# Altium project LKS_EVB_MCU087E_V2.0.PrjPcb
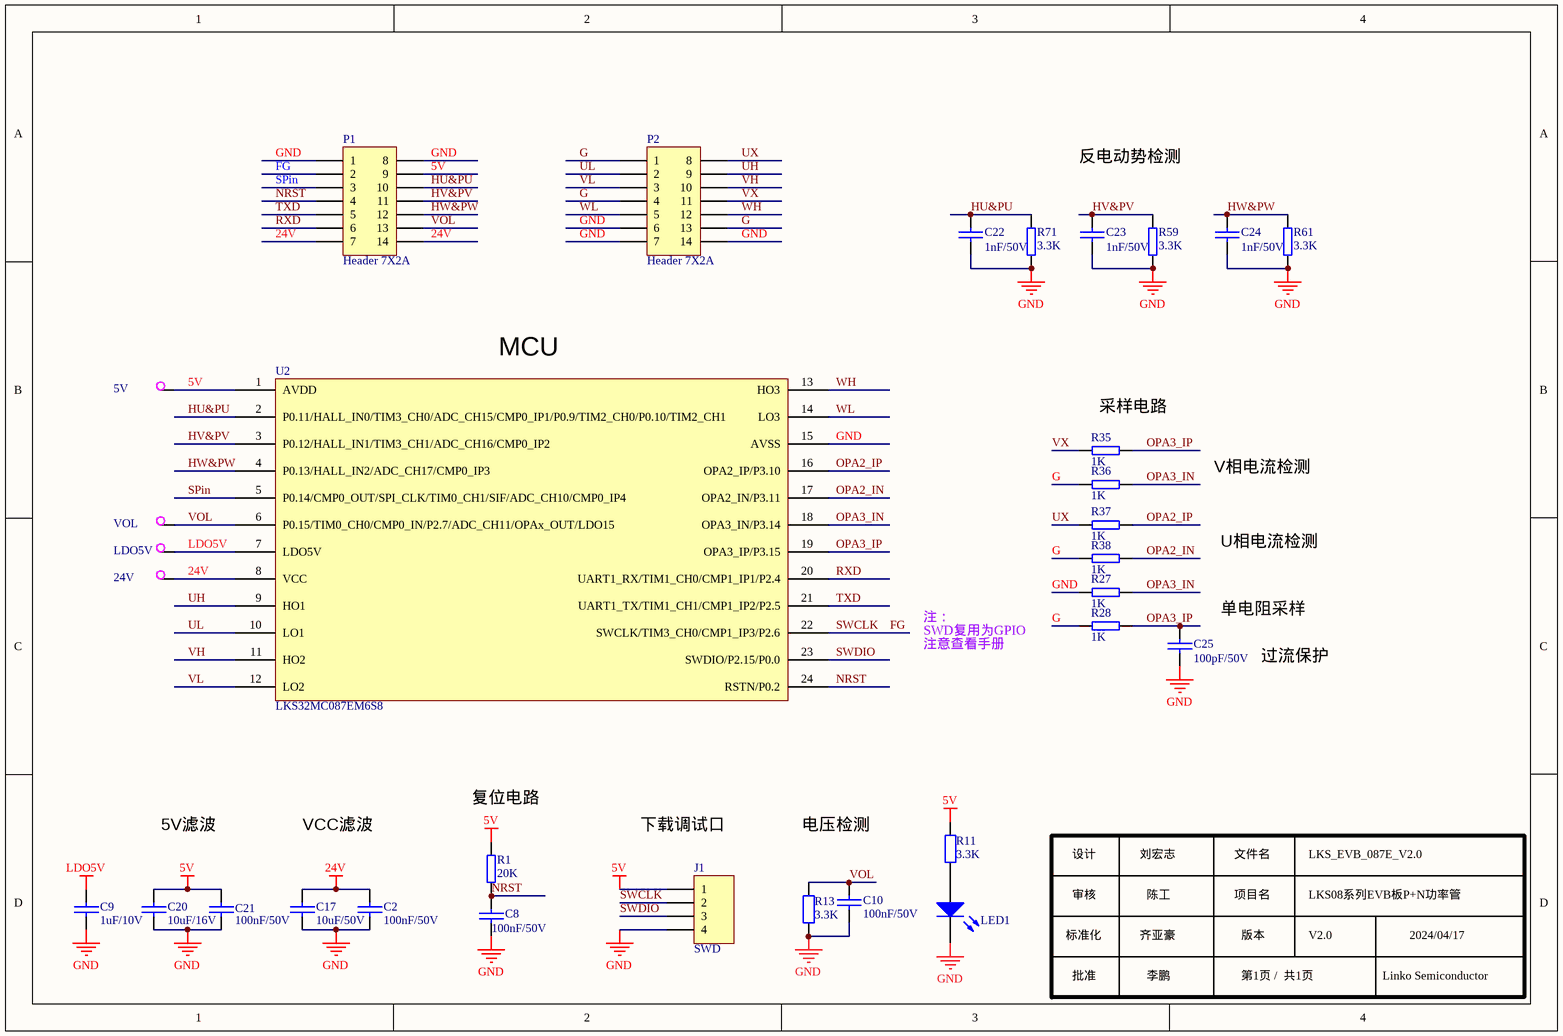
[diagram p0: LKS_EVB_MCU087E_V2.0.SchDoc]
1 sheet, 32 parts. Net scope: global (net labels, ports and power ports of the same name join across sheets).
Board file: LKS_EVB_MCU087E_V2.0.PcbDoc

## Sheet LKS_EVB_MCU087E_V2.0.SchDoc: LKS087_DEMO_V2.0_200109
size A4; Revision: V1.0; SheetNumber: 1; SheetTotal: 1

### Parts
5V  TestP  [TP-80]  (value not drawn)
24V  TestP  [TP-80]  (value not drawn)
C2  100nF/50V  [0603C]
C8  100nF/50V  [0603C]
C9  1uF/10V  [0603C]
C10  100nF/50V  [0603C]
C17  10uF/50V  [0805C]
C20  10uF/16V  [0603C]
C21  100nF/50V  [0603C]
C22  1nF/50V  [0603C]
C23  1nF/50V  [0603C]
C24  1nF/50V  [0603C]
C25  100pF/50V  [0603C]
J1  SWD  [SIP4-2.5]
LDO5V  TestP  [TP-80]  (value not drawn)
LED1  (no value)  [LED 0603R]
P1  Header 7X2A  [HDR2X7_CEN]
P2  Header 7X2A  [HDR2X7_CEN]
R1  20K  [0603R]
R11  3.3K  [0603R]
R13  3.3K  [0603R]
R27  1K  [0603R]
R28  1K  [0603R]
R35  1K  [0603R]
R36  1K  [0603R]
R37  1K  [0603R]
R38  1K  [0603R]
R59  3.3K  [0603R]
R61  3.3K  [0603R]
R71  3.3K  [0603R]
U2  LKS32MC087EM6S8  [SSOP24]
VOL  TestP  [TP-80]  (value not drawn)

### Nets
5V: 5V.1 C20.2 C21.1 J1.1 P1.9 R1.1 R11.2 U2.1(AVDD)
24V: 24V.1 C2.1 C17.2 P1.7 P1.14 U2.8(VCC)
GND: C2.2 C8.2 C9.2 C10.2 C17.1 C20.1 C21.2 C22.1 C23.1 C24.1 C25.1 J1.4 LED1.2(K) P1.1 P1.8 P2.6 P2.7 P2.14 R13.2 R27.2 R59.1 R61.1 R71.1 U2.15(AVSS)
LDO5V: C9.1 LDO5V.1 U2.7(LDO5V)
FG: J1.2 P1.2 U2.22(SWCLK/TIM3_CH0/CMP1_IP3/P2.6)  [also labelled SWCLK]
G: P2.1 P2.4 P2.13 R28.2 R36.1 R38.1
HU&PU: C22.2 P1.10 R71.2 U2.2(P0.11/HALL_IN0/TIM3_CH0/ADC_CH15/CMP0_IP1/P0.9/TIM2_CH0/P0.10/TIM2_CH1)
HV&PV: C23.2 P1.11 R59.2 U2.3(P0.12/HALL_IN1/TIM3_CH1/ADC_CH16/CMP0_IP2)
HW&PW: C24.2 P1.12 R61.2 U2.4(P0.13/HALL_IN2/ADC_CH17/CMP0_IP3)
NRST: C8.1 P1.4 R1.2 U2.24(RSTN/P0.2)
OPA2_IN: R38.2 U2.17(OPA2_IN/P3.11)
OPA2_IP: R37.2 U2.16(OPA2_IP/P3.10)
OPA3_IN: R27.1 R36.2 U2.18(OPA3_IN/P3.14)
OPA3_IP: C25.2 R28.1 R35.2 U2.19(OPA3_IP/P3.15)
RXD: P1.6 U2.20(UART1_RX/TIM1_CH0/CMP1_IP1/P2.4)
SPin: P1.3 U2.5(P0.14/CMP0_OUT/SPI_CLK/TIM0_CH1/SIF/ADC_CH10/CMP0_IP4)
SWDIO: J1.3 U2.23(SWDIO/P2.15/P0.0)
TXD: P1.5 U2.21(UART1_TX/TIM1_CH1/CMP1_IP2/P2.5)
UH: P2.9 U2.9(HO1)
UL: P2.2 U2.10(LO1)
UX: P2.8 R37.1
VH: P2.10 U2.11(HO2)
VL: P2.3 U2.12(LO2)
VOL: C10.1 P1.13 R13.1 U2.6(P0.15/TIM0_CH0/CMP0_IN/P2.7/ADC_CH11/OPAx_OUT/LDO15) VOL.1
VX: P2.11 R35.1
WH: P2.12 U2.13(HO3)
WL: P2.5 U2.14(LO3)
NetLED1_1: LED1.1(A) R11.1

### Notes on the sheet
- (near U2) MCU
- (near R35) 采样电路
- V相电流检测
- U相电流检测
- SWD复用为GPIO
- 注意查看手册
- 注：
- 过流保护
- 5V滤波
- VCC滤波
- (near R1) 复位电路
- 设计
- 审核
- 刘宏志
- 陈工
- 文件名
- 项目名
- LKS_EVB_087E_V2.0
- LKS08系列EVB板P+N功率管
- 标准化
- 批准
- 齐亚豪
- 李鹏
- 版本
- 第1页 /  共1页
- V2.0
- Linko Semiconductor
- 2024/04/17
- Labels drawn without touching a wire or pin: 下载调试口, 单电阻采样, 反电动势检测, 电压检测

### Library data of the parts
C2 C10 C17 C20 C21 = CAP: Capacitor
C8 C9 C22-C25 = C: Capacitor
J1 = Header 4: Header, 4-Pin
LED1 = LED2: Typical RED, GREEN, YELLOW, AMBER GaAs LED
P1 P2 = Header 7X2A: Header, 7-Pin, Dual row
R1 R27 R28 R35-R38 = RES2-1
R11 R13 = Res2: Resistor
R59 R61 R71 = RES/1
U2 = LKS32MC087EM6S8: 芯片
